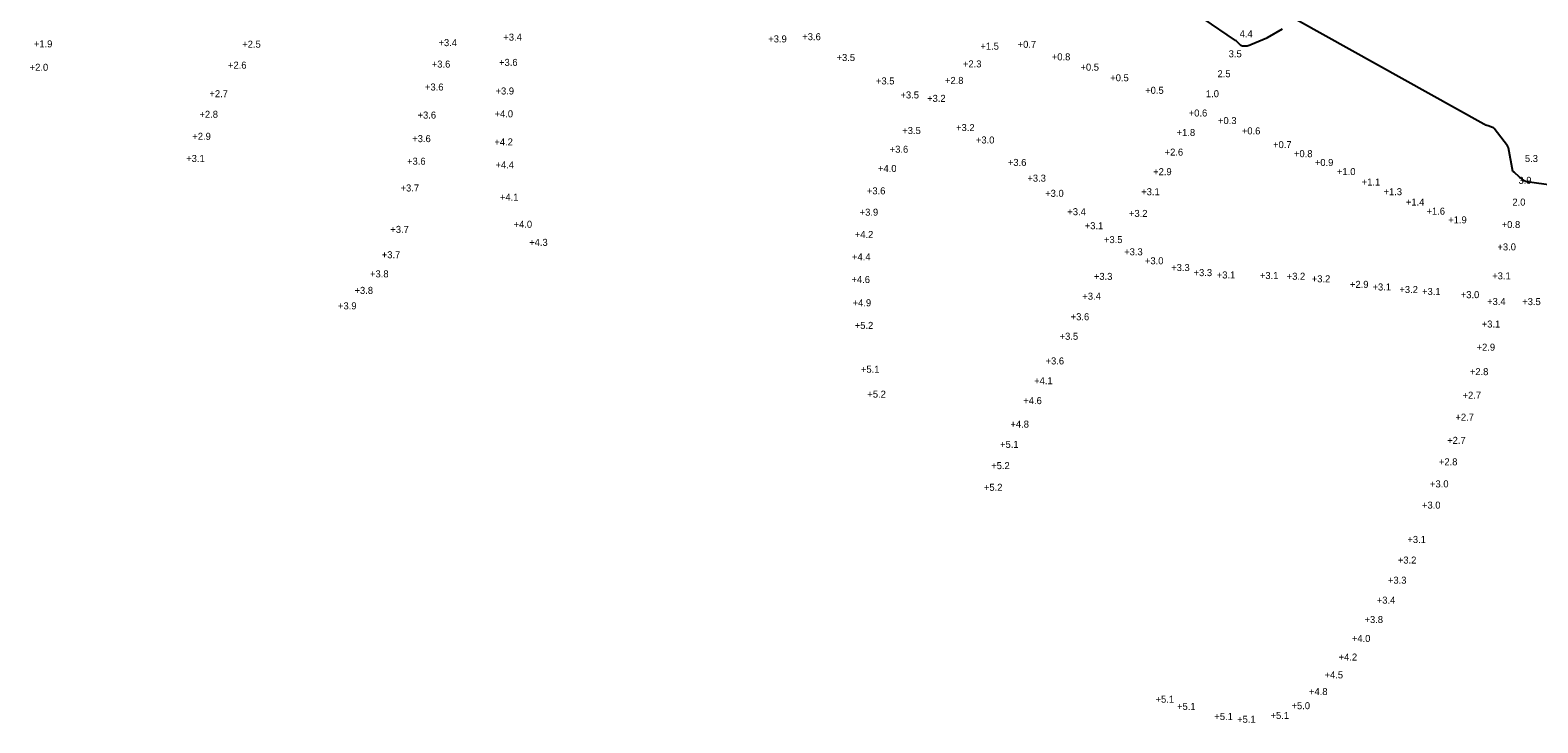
# Model space of a CAD drawing. Extents: x 837127 to 848654, y 3074248 to 3079868.
# Drawn here: x 843849 to 844521, y 3078957 to 3079266 of the extents above; entities that cross this region are included whole.
import ezdxf

# ---------------------------------------------------------------- set-up
doc = ezdxf.new("R2010")
doc.units = 0
for name, color, linetype in [('V-HYDS-MAJR', 7, 'Continuous'), ('V-HYDS-SOUN', 7, 'Continuous'), ('V-HYDS-SOUN-EXSS', 7, 'Continuous')]:
    doc.layers.add(name, color=color, linetype=linetype)

msp = doc.modelspace()

# ---------------------------------------------------------------- linework, layer by layer
at = {"layer": 'V-HYDS-MAJR'}
for points in [[(844406.68, 3079266.43), (844400.02, 3079262.59), (844399.89, 3079262.51), (844399.76, 3079262.46), (844392.69, 3079259.52), (844392.34, 3079259.28), (844391.96, 3079259.1), (844391.56, 3079258.99), (844391.13, 3079258.94), (844389.33, 3079258.89), (844388.92, 3079258.92), (844388.55, 3079259.02), (844388.21, 3079259.2), (844387.9, 3079259.46), (844386.73, 3079260.65), (844386.43, 3079260.93), (844386.12, 3079261.21), (844385.79, 3079261.47), (844385.46, 3079261.71), (844371.9, 3079270.96)], [(844526.3, 3079196.88), (844516.82, 3079198.29), (844515.98, 3079198.31), (844515.19, 3079198.5), (844514.46, 3079198.84), (844513.79, 3079199.34), (844510.31, 3079202.46), (844510.1, 3079202.62), (844509.88, 3079202.76), (844509.65, 3079202.88), (844509.41, 3079202.97), (844507.46, 3079213.5), (844507.4, 3079213.87), (844507.25, 3079214.18), (844507, 3079214.43), (844501.1, 3079222.1), (844500.81, 3079222.4), (844500.37, 3079222.61), (844498.39, 3079223.29), (844497.9, 3079223.46), (844497.42, 3079223.67), (844496.95, 3079223.89), (844496.49, 3079224.13), (844413.05, 3079270.56)]]:
    msp.add_lwpolyline(points, dxfattribs=at)

# ---------------------------------------------------------------- texts
at = {"layer": 'V-HYDS-SOUN'}
for s, p in [('+3.4 ', (844059.71, 3079261.33)), ('+3.6 ', (844192.88, 3079261.54)), ('4.4', (844387.73, 3079262.84)), ('+1.9 ', (843850.56, 3079258.33)), ('+2.5 ', (843943.4, 3079258.19)), ('+3.4 ', (844030.82, 3079258.88)), ('+3.9 ', (844177.73, 3079260.54)), ('+1.5 ', (844272.23, 3079257.3)), ('+0.7 ', (844288.83, 3079258.12)), ('+2.0 ', (843848.71, 3079247.9)), ('+2.6 ', (843937.05, 3079248.83)), ('+3.6 ', (844027.83, 3079249.32)), ('+3.6 ', (844057.81, 3079250.08)), ('+3.5 ', (844208.14, 3079252.26)), ('+2.3 ', (844264.45, 3079249.4)), ('+0.8 ', (844304.04, 3079252.55)), ('+0.5 ', (844316.81, 3079247.95)), ('3.5', (844382.83, 3079253.9)), ('+3.5 ', (844225.7, 3079241.81)), ('+2.8 ', (844256.44, 3079242.04)), ('+0.5 ', (844330.08, 3079243.23)), ('2.5', (844377.86, 3079245.02)), ('+2.7 ', (843928.77, 3079236.13)), ('+3.6 ', (844024.8, 3079239.11)), ('+3.9 ', (844056.23, 3079237.33)), ('+3.5 ', (844236.62, 3079235.57)), ('+3.2 ', (844248.49, 3079234.04)), ('+0.5 ', (844345.64, 3079237.63)), ('1.0', (844372.7, 3079236.12)), ('+0.6 ', (844365.04, 3079227.52)), ('+2.8 ', (843924.33, 3079226.93)), ('+3.6 ', (844021.5, 3079226.6)), ('+4.0 ', (844055.79, 3079227.16)), ('+3.2 ', (844261.4, 3079221.03)), ('+0.3 ', (844378.09, 3079224.15)), ('+2.9 ', (843921.16, 3079217.13)), ('+3.6 ', (844019.13, 3079216.09)), ('+4.2 ', (844055.72, 3079214.63)), ('+3.5 ', (844237.43, 3079219.69)), ('+3.0 ', (844270.23, 3079215.5)), ('+1.8 ', (844359.65, 3079218.83)), ('+0.6 ', (844388.7, 3079219.55)), ('+3.6 ', (844231.83, 3079211.37)), ('+2.6 ', (844354.3, 3079210.1)), ('+0.7 ', (844402.61, 3079213.44)), ('+0.8 ', (844411.92, 3079209.39)), ('5.3', (844514.8, 3079207.23)), ('+3.6 ', (844016.82, 3079206.03)), ('+4.4 ', (844056.2, 3079204.4)), ('+4.0 ', (844226.61, 3079202.8)), ('+3.6 ', (844284.47, 3079205.49)), ('+2.9 ', (844349.19, 3079201.36)), ('+0.9 ', (844421.22, 3079205.48)), ('+1.0 ', (844431.07, 3079201.42)), ('+3.7 ', (844013.93, 3079194.1)), ('+3.3 ', (844293.17, 3079198.49)), ('+1.1 ', (844442.09, 3079196.76)), ('3.9', (844511.94, 3079197.49)), ('+4.1 ', (844058.19, 3079189.99)), ('+3.6 ', (844221.66, 3079192.83)), ('+3.0 ', (844301.09, 3079191.72)), ('+3.1 ', (844343.88, 3079192.43)), ('+1.3 ', (844451.81, 3079192.45)), ('+1.4 ', (844461.78, 3079187.83)), ('2.0', (844509.23, 3079187.81)), ('+3.9 ', (844218.45, 3079183.31)), ('+3.4 ', (844310.96, 3079183.53)), ('+3.2 ', (844338.42, 3079182.76)), ('+1.6 ', (844470.96, 3079183.77)), ('+3.7 ', (844009.38, 3079175.65)), ('+4.0 ', (844064.28, 3079177.93)), ('+3.1 ', (844318.71, 3079177.29)), ('+1.9 ', (844480.64, 3079179.89)), ('+0.8 ', (844504.47, 3079177.8)), ('+4.3 ', (844071.22, 3079169.86)), ('+4.2 ', (844216.27, 3079173.39)), ('+3.5 ', (844327.29, 3079171.09)), ('+3.0 ', (844502.56, 3079167.83)), ('+3.7 ', (844005.55, 3079164.35)), ('+4.4 ', (844215.05, 3079163.39)), ('+3.3 ', (844336.28, 3079165.66)), ('+3.0 ', (844345.53, 3079161.65)), ('+3.8 ', (844000.33, 3079155.82)), ('+3.3 ', (844322.79, 3079154.69)), ('+3.3 ', (844357.22, 3079158.63)), ('+3.3 ', (844367.21, 3079156.37)), ('+3.1 ', (844377.52, 3079155.33)), ('+3.1 ', (844396.73, 3079155.09)), ('+3.2 ', (844408.68, 3079154.75)), ('+3.2 ', (844419.85, 3079153.63)), ('+3.1 ', (844500.22, 3079154.93)), ('+3.8 ', (843993.42, 3079148.46)), ('+4.6 ', (844214.79, 3079153.29)), ('+2.9 ', (844436.87, 3079151.14)), ('+3.1 ', (844446.9, 3079149.97)), ('+3.2 ', (844458.89, 3079148.85)), ('+3.1 ', (844468.99, 3079147.96)), ('+3.9 ', (843986.07, 3079141.56)), ('+4.9 ', (844215.31, 3079142.94)), ('+3.4 ', (844317.65, 3079145.85)), ('+3.0 ', (844486.22, 3079146.55)), ('+3.4 ', (844497.96, 3079143.51)), ('+3.5 ', (844513.61, 3079143.46)), ('+3.6 ', (844312.46, 3079136.71)), ('+3.1 ', (844495.57, 3079133.45)), ('+5.2 ', (844216.25, 3079132.85)), ('+3.5 ', (844307.52, 3079128)), ('+2.9 ', (844493.27, 3079123.15)), ('+5.1 ', (844219.01, 3079113.31)), ('+3.6 ', (844301.26, 3079117.01)), ('+4.1 ', (844296.16, 3079108.18)), ('+2.8 ', (844490.27, 3079112.23)), ('+5.2 ', (844221.88, 3079102.22)), ('+2.7 ', (844487.03, 3079101.72)), ('+4.6 ', (844291.34, 3079099.33)), ('+4.8 ', (844285.61, 3079088.85)), ('+2.7 ', (844483.85, 3079091.97)), ('+5.1 ', (844281, 3079079.83)), ('+2.7 ', (844480.17, 3079081.61)), ('+5.2 ', (844277.06, 3079070.35)), ('+2.8 ', (844476.49, 3079072.05)), ('+5.2 ', (844273.8, 3079060.68)), ('+3.0 ', (844472.54, 3079062.2)), ('+3.0 ', (844468.95, 3079052.75)), ('+3.1 ', (844462.46, 3079037.45)), ('+3.2 ', (844458.2, 3079028.26)), ('+3.3 ', (844453.78, 3079019.28)), ('+3.4 ', (844448.81, 3079010.4)), ('+3.8 ', (844443.35, 3079001.74)), ('+4.0 ', (844437.72, 3078993.32)), ('+4.2 ', (844431.82, 3078985.02)), ('+4.5 ', (844425.54, 3078977.08)), ('+5.1 ', (844350.27, 3078966.23)), ('+4.8 ', (844418.62, 3078969.64)), ('+5.1 ', (844359.84, 3078963.02)), ('+5.1 ', (844401.5, 3078959.01)), ('+5.0 ', (844410.83, 3078963.35)), ('+5.1 ', (844376.46, 3078958.54)), ('+5.1 ', (844386.6, 3078957.3))]:
    msp.add_text(s, height=3.125, dxfattribs=at).set_placement(p)
at = {"layer": 'V-HYDS-SOUN-EXSS'}
msp.add_text('+3.1 ', height=3.125, dxfattribs=at).set_placement((843918.43, 3079207.27))

doc.saveas('drawing.dxf')
